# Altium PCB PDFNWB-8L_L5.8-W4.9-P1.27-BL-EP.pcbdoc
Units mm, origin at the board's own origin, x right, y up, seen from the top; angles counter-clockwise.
Board outline 17.69 x 19.74 mm, 2 copper layers (Top Layer, Bottom Layer), stack 0 mm thick; 1 components, 0 nets, 9 pads, 0 vias.
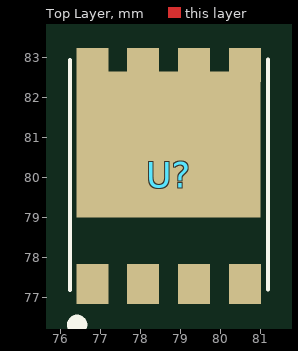
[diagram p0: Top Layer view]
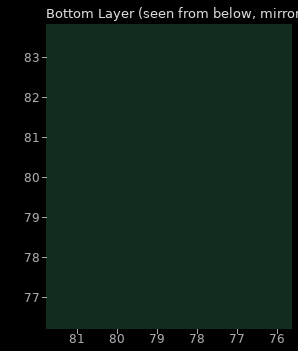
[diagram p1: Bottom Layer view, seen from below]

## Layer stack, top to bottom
Top Layer: signal copper (thickness not stored)
Bottom Layer: signal copper (thickness not stored)

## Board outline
87.54,69.85 69.85,69.85 69.85,89.593 87.54,89.593

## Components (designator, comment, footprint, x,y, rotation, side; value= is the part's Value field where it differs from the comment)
U? "" PDFNWB-8L_L5.8-W4.9-P1.27-BL-EP 78.71,80.08 r0 top

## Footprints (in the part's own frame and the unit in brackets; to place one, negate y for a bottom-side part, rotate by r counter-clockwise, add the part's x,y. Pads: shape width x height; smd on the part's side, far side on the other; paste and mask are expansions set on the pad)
PDFNWB-8L_L5.8-W4.9-P1.27-BL-EP [mm]
  rect 0.8x1 smd paste-100 mask+0.05: 1(-1.905,-2.737) 2(-0.635,-2.737) 3(0.635,-2.737) 4(1.905,-2.737)
  rect 0.8x0.85 smd paste-100 mask+0.05: 5(1.905,2.738) 6(0.635,2.738) 7(-0.635,2.738) 8(-1.905,2.738)
  rect 4.6x3.65 smd paste-100 mask+0.05: 9(-0.005,0.76)
  silkscreen extent -2.46,-3.88 2.48,2.88

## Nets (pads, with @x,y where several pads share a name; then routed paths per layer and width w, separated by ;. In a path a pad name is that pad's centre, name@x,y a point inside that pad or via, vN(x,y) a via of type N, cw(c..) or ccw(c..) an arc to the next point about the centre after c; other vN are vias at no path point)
pads on no net: U?.1 U?.2 U?.3 U?.4 U?.5 U?.6 U?.7 U?.8 U?.9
